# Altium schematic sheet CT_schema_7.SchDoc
size 274 x 160 mm
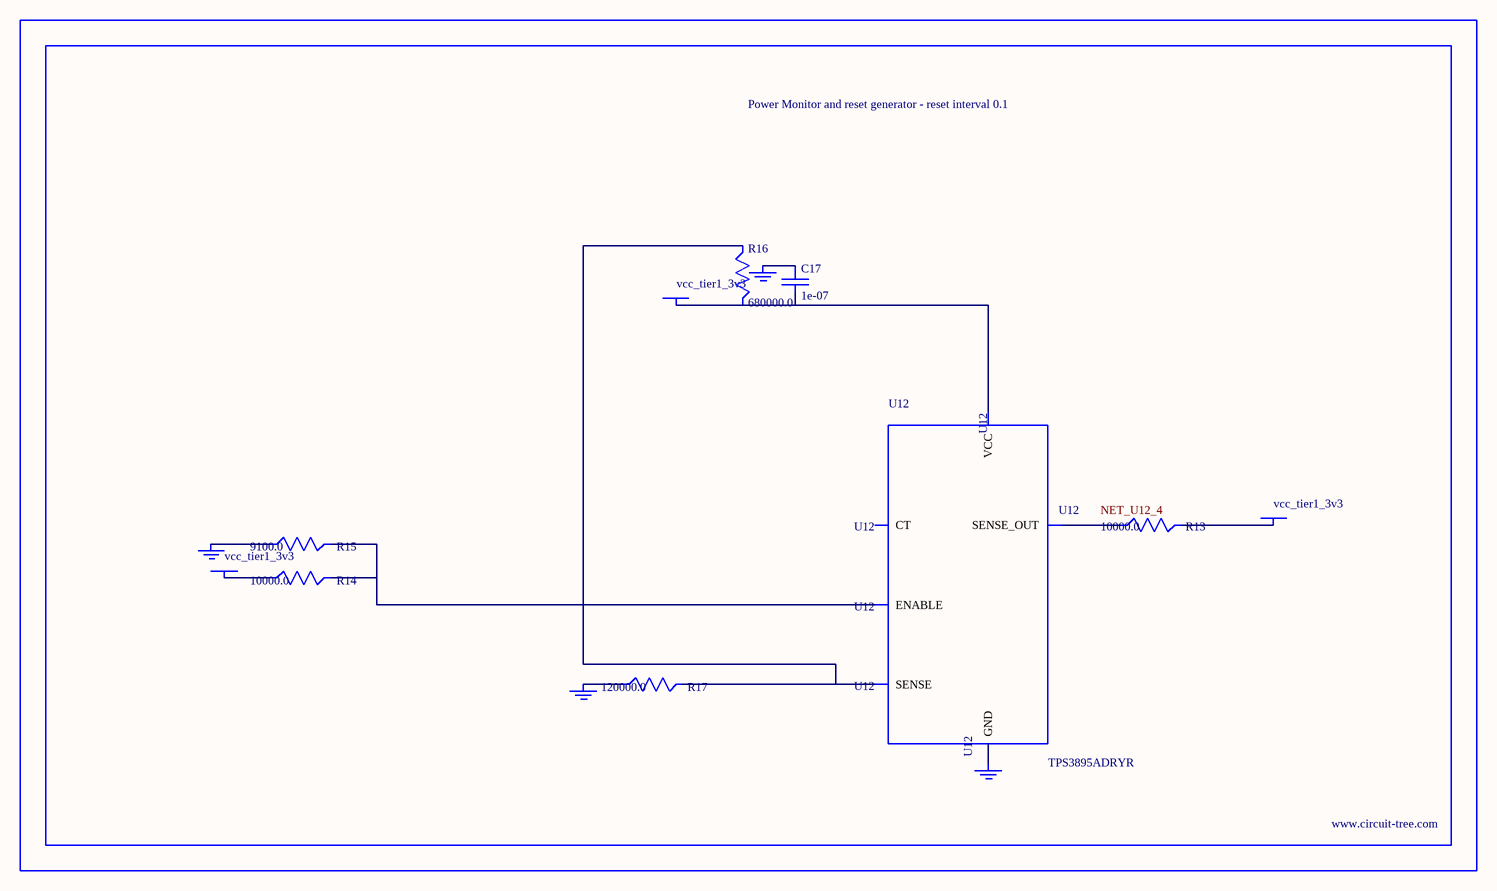
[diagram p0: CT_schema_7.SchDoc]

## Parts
BORDER6  (no value)
C17  1e-07  [C0402]
GND_INSTANCE_6_0  (no value)
GND_INSTANCE_6_1  (no value)
GND_INSTANCE_6_2  (no value)
GND_INSTANCE_6_3  (no value)
POWER_INSTANCE_6_0  vcc_tier1_3v3
POWER_INSTANCE_6_1  vcc_tier1_3v3
POWER_INSTANCE_6_2  vcc_tier1_3v3
R13  10000.0  [R0603]
R14  10000.0  [R0603]
R15  9100.0  [R0603]
R16  680000.0  [R0603]
R17  120000.0  [R0603]
U12  TPS3895ADRYR  [SON-6]

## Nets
NetC17_1: C17.1 GND_INSTANCE_6_2.0(GND)
NetC17_2: C17.2 POWER_INSTANCE_6_2.0(PWR) R16.2 U12.6(VCC)
NetGND_INSTANCE_6_0_0: GND_INSTANCE_6_0.0(GND) R15.1
NetGND_INSTANCE_6_1_0: GND_INSTANCE_6_1.0(GND) R17.1
NetGND_INSTANCE_6_3_0: GND_INSTANCE_6_3.0(GND) U12.2(GND)
NetPOWER_INSTANCE_6_0_0: POWER_INSTANCE_6_0.0(PWR) R14.1
NetPOWER_INSTANCE_6_1_0: POWER_INSTANCE_6_1.0(PWR) R13.2
NetR13_1: R13.1 U12.4(SENSE_OUT)
NetR14_2: R14.2 R15.2 U12.1(ENABLE)
NetR16_1: R16.1 R17.2 U12.3(SENSE)

Not connected (* = marked no-connect by the designer): U12 5(CT)

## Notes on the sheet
- Labels drawn without touching a wire or pin: NET_U12_4

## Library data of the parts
BORDER6 = BORDER_PAGE6
C17 = C0402C104K3RACTU
GND_INSTANCE_6_0-GND_INSTANCE_6_3 = GND
POWER_INSTANCE_6_0-POWER_INSTANCE_6_2 = PWR
R13 R14 = RC0603JR-0710KL
R15 = RC0603JR-079K1L
R16 = RC0603JR-07680KL
R17 = RC0603JR-07120KL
